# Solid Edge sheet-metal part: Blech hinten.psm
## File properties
Author: heha
Template: Normal.psm
Last saved by: heha
Revision: 10
Application: Solid Edge
Materialstärke: 1,50 mm
Biegeradius: 1,50 mm
Ausklinkungsbreite: 1,50 mm
Ausklinkungslänge: 1,50 mm
Neutralfaktor: 0,330
Dichte: 2,712 kg/dm^3
Genauigkeit: 0,990
Minimale Bogenlänge: 0,10 mm
Abweichungstoleranz: 0,10 mm
Material: Aluminium, 1060
Teilflächenformatvorlage: Aluminium
Füllformatvorlage: ANSI38(Aluminum)
Virtuelle Formatvorlage: Poliertes Aluminium
Coef. of Thermal Exp: 2.3e-05
Thermal Conductivity: 221.0
Specific Heat: 920.0
Modulus of Elasticity: 68947570000.0
Poission's Ratio: 0.33
Yield Stress: 27579028.0
Ultimate Stress: 68947570.0
Elongation: 0.0
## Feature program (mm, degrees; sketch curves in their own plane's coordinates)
base tab "unnamed BaseTab 1"
sheet metal cutout "unnamed SheetMetalCutout 1"
sheet metal cutout "unnamed SheetMetalCutout 2"
pattern "unnamed Pattern 1" of "unnamed SheetMetalCutout 2"
sheet metal cutout "unnamed SheetMetalCutout 3"
sheet metal cutout "unnamed SheetMetalCutout 4"
sheet metal cutout "unnamed SheetMetalCutout 5"
sheet metal cutout "unnamed SheetMetalCutout 6"
sheet metal cutout "unnamed SheetMetalCutout 7"
sheet metal cutout "unnamed SheetMetalCutout 8"
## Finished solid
Body 1: solid body, 44 faces, 104 edges, 40 vertices.
  Faces by surface: cylinder 26, plane 18
  Edges by curve: circle 52, line 52
Bounding box of the edges (mm): 103.000 x 1.500 x 56.000, from (-51.5, -1.5, -28) to (51.5, 0, 28).
Cylindrical faces by radius (mm): R1.5 x12, R1.6 x4, R2 x4, R7.5 x6
Planar faces by outward normal: +x 4, +y 1, +z 6, -x 4, -y 1, -z 2
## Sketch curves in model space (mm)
line (49.5, 0, 21.2) -> (49.5, 0, 19.4)
line (49.5, 0, 19.4) -> (-49.5, 0, 19.4)
line (-49.5, 0, 19.4) -> (-49.5, 0, 21.2)
line (-49.5, 0, 21.2) -> (49.5, 0, 21.2)
line (24.62, 0, 19.4) -> (41.42, 0, 19.4)
line (41.42, 0, 19.4) -> (41.42, 0, 10.6)
line (41.42, 0, 10.6) -> (24.62, 0, 10.6)
line (24.62, 0, 10.6) -> (24.62, 0, 19.4)
line (49.5, 0, -19.4) -> (49.5, 0, -21.2)
line (49.5, 0, -21.2) -> (-49.5, 0, -21.2)
line (-49.5, 0, -21.2) -> (-49.5, 0, -19.4)
line (-49.5, 0, -19.4) -> (49.5, 0, -19.4)
circle centre (-24.1259, 0, -3.1) radius 1.5
circle centre (-41.8741, 0, -16.1) radius 1.5
circle centre (-33, 0, -9.6) radius 7.5
line (-33, 0, -9.6) -> (-23.0358, 0, -9.6)
line (-41.8741, 0, -16.1) -> (-24.1259, 0, -3.1)
arc centre (-33, 0, -9.6) radius 9.5 from (-42.0575, 0, -6.7343) through (-38.6136, 0, -1.936) to (-33, 0, -0.1)
line (-33, 0, -0.1) -> (-24.1259, 0, -0.1)
arc centre (-24.1259, 0, -3.1) radius 3 from (-24.1259, 0, -0.1) through (-21.7057, 0, -1.3273) to (-21.2656, 0, -4.005)
line (-21.2656, 0, -4.005) -> (-23.9425, 0, -12.4657)
arc centre (-33, 0, -9.6) radius 9.5 from (-23.9425, 0, -12.4657) through (-27.3864, 0, -17.264) to (-33, 0, -19.1)
line (-33, 0, -19.1) -> (-41.8741, 0, -19.1)
arc centre (-41.8741, 0, -16.1) radius 3 from (-41.8741, 0, -19.1) through (-44.2943, 0, -17.8727) to (-44.7344, 0, -15.195)
line (-44.7344, 0, -15.195) -> (-42.0575, 0, -6.7343)
circle centre (-47.5, 0, -24) radius 1.3
line (-41.5, 0, -27) -> (0, 0, -27)
line (-41.5, 0, -25.2) -> (0, 0, -25.2)
line (-41.5, 0, -28) -> (-41.5, 0, -27)
line (-49.5, 0, -28) -> (-41.5, 0, -28)
arc centre (-49.5, 0, -26) radius 2 from (-51.5, 0, -26) through (-50.8725, 0, -27.4547) to (-49.5, 0, -28)
line (-51.5, 0, 26) -> (-51.5, 0, -26)
arc centre (-49.5, 0, 26) radius 2 from (-49.5, 0, 28) through (-50.9547, 0, 27.3725) to (-51.5, 0, 26)
line (-41.5, 0, 28) -> (-49.5, 0, 28)
line (-44.5, 0, -25.2) -> (-41.5, 0, -25.2)
line (-44.5, 0, -27) -> (-44.5, 0, -25.2)
line (-41.5, 0, -27) -> (-44.5, 0, -27)
line (-47.5, 0, 0.9) -> (-47.5, 0, 2)
line (-49.5, 0, 0.9) -> (-47.5, 0, 0.9)
line (-49.5, 0, -0.9) -> (-49.5, 0, 0.9)
line (-47.5, 0, -0.9) -> (-49.5, 0, -0.9)
line (-47.5, 0, -2) -> (-47.5, 0, -0.9)
line (-49.5, 0, -2) -> (-47.5, 0, -2)
line (-49.5, 0, -3.8) -> (-49.5, 0, -2)
line (-47.5, 0, -3.8) -> (-49.5, 0, -3.8)
line (-47.5, 0, -4.9) -> (-47.5, 0, -3.8)
line (-49.5, 0, -4.9) -> (-47.5, 0, -4.9)
line (-49.5, 0, -6.7) -> (-49.5, 0, -4.9)
line (-47.5, 0, -6.7) -> (-49.5, 0, -6.7)
line (-47.5, 0, -7.8) -> (-47.5, 0, -6.7)
line (-49.5, 0, -7.8) -> (-47.5, 0, -7.8)
line (-49.5, 0, -9.6) -> (-49.5, 0, -7.8)
line (-47.5, 0, -9.6) -> (-49.5, 0, -9.6)
line (-47.5, 0, -10.7) -> (-47.5, 0, -9.6)
line (-49.5, 0, -10.7) -> (-47.5, 0, -10.7)
line (-49.5, 0, -12.5) -> (-49.5, 0, -10.7)
line (-47.5, 0, -12.5) -> (-49.5, 0, -12.5)
line (-47.5, 0, -13.6) -> (-47.5, 0, -12.5)
line (-49.5, 0, -13.6) -> (-47.5, 0, -13.6)
line (-49.5, 0, -15.4) -> (-49.5, 0, -13.6)
line (-47.5, 0, -15.4) -> (-49.5, 0, -15.4)
line (-47.5, 0, -16.5) -> (-47.5, 0, -15.4)
line (-49.5, 0, -16.5) -> (-47.5, 0, -16.5)
line (-49.5, 0, -18.3) -> (-49.5, 0, -16.5)
line (-47.5, 0, -18.3) -> (-49.5, 0, -18.3)
line (-47.5, 0, -19.4) -> (-47.5, 0, -18.3)
line (-49.5, 0, -19.4) -> (-47.5, 0, -19.4)
line (-49.5, 0, -21.2) -> (-49.5, 0, -19.4)
line (-41.5, 0, -21.2) -> (-49.5, 0, -21.2)
line (-41.5, 0, -25.2) -> (-41.5, 0, -21.2)
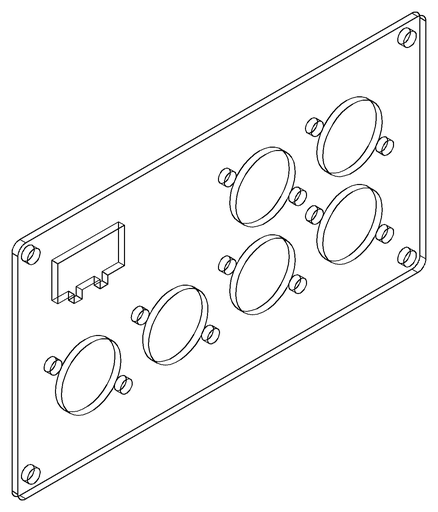
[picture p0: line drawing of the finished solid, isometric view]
